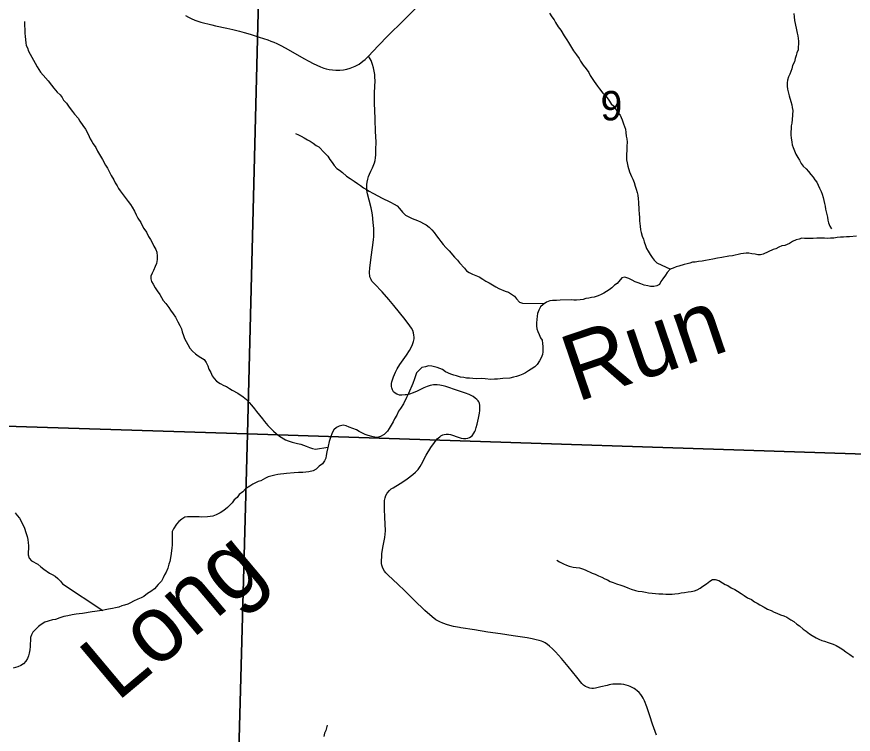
# Model space of a CAD drawing. Extents: x -3.3 to 34, y 0 to 56.8.
# Drawn here: x -0.715 to 0.477, y 29.247 to 30.269 of the extents above; entities that cross this region are included whole.
import ezdxf

# ---------------------------------------------------------------- set-up
doc = ezdxf.new("R2010")
doc.units = 0
for name, color, linetype in [('GM_X_Corporation', 7, 'Continuous'), ('GM_X_County_Road', 7, 'Continuous'), ('GM_X_Section_Text', 7, 'Continuous'), ('GM_X_Township_Road', 7, 'Continuous'), ('GT_Project_Cells', 7, 'Continuous'), ('GT_Project_Soil_Layers', 7, 'Continuous')]:
    doc.layers.add(name, color=color, linetype=linetype)

msp = doc.modelspace()

# ---------------------------------------------------------------- linework, layer by layer
at = {"layer": 'GM_X_Corporation'}
for points in [[(-0.3611, 30.6698), (-0.3862, 29.675), (-1.3918, 29.7067), (-1.3637, 30.7035)], [(-0.3611, 30.6698), (0.6593, 30.6334), (0.6247, 29.6418), (-0.3862, 29.675)], [(-1.3918, 29.7067), (-0.3862, 29.675), (-0.4137, 28.6668), (-1.4193, 28.6974)], [(0.6247, 29.6418), (0.5878, 28.6278), (-0.4137, 28.6668), (-0.3862, 29.675)]]:
    msp.add_lwpolyline(points, close=True, dxfattribs=at)
at = {"layer": 'GM_X_County_Road'}
msp.add_lwpolyline([(-0.4744, 30.271), (-0.4705, 30.2687), (-0.4665, 30.2666), (-0.4613, 30.2645), (-0.4571, 30.263), (-0.4528, 30.2617), (-0.4372, 30.2576), (-0.4317, 30.2564), (-0.4156, 30.253), (-0.4073, 30.2512), (-0.3978, 30.2488), (-0.391, 30.247), (-0.3822, 30.2444), (-0.3695, 30.2403), (-0.3573, 30.2363), (-0.353, 30.2347), (-0.3487, 30.2331), (-0.3446, 30.2312), (-0.3379, 30.2278), (-0.3284, 30.2227), (-0.3059, 30.2098), (-0.2987, 30.2059), (-0.2926, 30.2026), (-0.2873, 30.2003), (-0.2821, 30.198), (-0.2774, 30.1961), (-0.2739, 30.195), (-0.2699, 30.1941), (-0.265, 30.1934), (-0.2603, 30.193), (-0.2548, 30.1932), (-0.2495, 30.1936), (-0.2445, 30.1946), (-0.24, 30.1958), (-0.2329, 30.1989), (-0.2271, 30.2019), (-0.2216, 30.2058), (-0.2183, 30.2084), (-0.2136, 30.2133), (-0.2071, 30.22), (-0.1994, 30.2284), (-0.1861, 30.2423), (-0.1639, 30.264), (-0.1389, 30.2885)], dxfattribs=at)
at = {"layer": 'GM_X_Township_Road'}
for points in [[(-0.0822, 29.3984), (-0.0842, 29.3987), (-0.0927, 29.4004), (-0.101, 29.4026), (-0.1075, 29.4049), (-0.1121, 29.4069), (-0.1175, 29.4099), (-0.1231, 29.4141), (-0.1335, 29.4233), (-0.1488, 29.4379), (-0.1621, 29.451), (-0.1721, 29.4608), (-0.1857, 29.4734), (-0.189, 29.4769), (-0.1907, 29.4791), (-0.1927, 29.4823), (-0.1938, 29.4849), (-0.1946, 29.4876), (-0.195, 29.4899), (-0.1952, 29.4928), (-0.1949, 29.5008), (-0.1945, 29.5042), (-0.1927, 29.5153), (-0.1905, 29.5273), (-0.19, 29.5319), (-0.1897, 29.5365), (-0.1904, 29.5561), (-0.191, 29.5673), (-0.1907, 29.5799), (-0.1899, 29.5836), (-0.1888, 29.5868), (-0.1871, 29.5901), (-0.184, 29.5943), (-0.1813, 29.5964), (-0.1786, 29.5981), (-0.1686, 29.6039), (-0.1633, 29.6072), (-0.1585, 29.6106), (-0.1505, 29.6168), (-0.1465, 29.6203), (-0.1445, 29.6225), (-0.143, 29.6242), (-0.14, 29.6284), (-0.138, 29.6317), (-0.1313, 29.6444), (-0.1247, 29.6555), (-0.1197, 29.6627), (-0.1158, 29.6679), (-0.1122, 29.6708), (-0.1107, 29.6718), (-0.1078, 29.6734), (-0.1059, 29.674), (-0.1031, 29.6743), (-0.0995, 29.6743), (-0.0968, 29.6738), (-0.0845, 29.6698), (-0.0817, 29.6688), (-0.0781, 29.6682), (-0.0749, 29.6681), (-0.0722, 29.6687), (-0.0695, 29.6698), (-0.066, 29.6722), (-0.0634, 29.6759), (-0.0621, 29.6782), (-0.0613, 29.6801), (-0.0601, 29.6839), (-0.0589, 29.6886), (-0.0569, 29.6973), (-0.0554, 29.7042), (-0.055, 29.7079), (-0.0551, 29.7152), (-0.0556, 29.7185), (-0.0564, 29.7205), (-0.0574, 29.7221), (-0.0591, 29.7239), (-0.0615, 29.7259), (-0.0643, 29.7279), (-0.0675, 29.7297), (-0.07, 29.7308), (-0.0753, 29.7328), (-0.0869, 29.7366), (-0.1034, 29.7421), (-0.1074, 29.7433), (-0.1121, 29.7444), (-0.1156, 29.7448), (-0.121, 29.7447), (-0.1234, 29.7443), (-0.1259, 29.7437), (-0.1301, 29.7424), (-0.1347, 29.7405), (-0.1443, 29.7358), (-0.1502, 29.7333), (-0.1551, 29.7316), (-0.1594, 29.7306), (-0.1615, 29.7303), (-0.166, 29.73), (-0.1697, 29.7302), (-0.1718, 29.7308), (-0.1735, 29.7315), (-0.1759, 29.7329), (-0.1781, 29.7346), (-0.1797, 29.7375), (-0.1806, 29.7402), (-0.181, 29.7425), (-0.1811, 29.7449), (-0.1808, 29.7468), (-0.1803, 29.7492), (-0.1779, 29.7562), (-0.175, 29.7629), (-0.1726, 29.7673), (-0.1689, 29.7735), (-0.1596, 29.7868), (-0.1553, 29.7934), (-0.1524, 29.7989), (-0.1508, 29.8024), (-0.1495, 29.8064), (-0.1488, 29.8104), (-0.1486, 29.8128), (-0.1489, 29.8156), (-0.1496, 29.8187), (-0.1507, 29.8222), (-0.1525, 29.8255), (-0.1548, 29.8288), (-0.1614, 29.8377), (-0.1693, 29.8478), (-0.1774, 29.8579), (-0.1845, 29.8662), (-0.1944, 29.8773), (-0.2051, 29.8884), (-0.2075, 29.8909), (-0.2088, 29.8926), (-0.2101, 29.8948), (-0.2108, 29.8965), (-0.2116, 29.8988), (-0.212, 29.9011), (-0.2122, 29.9028), (-0.2121, 29.9051), (-0.2116, 29.9111), (-0.2097, 29.9264), (-0.208, 29.9404), (-0.2066, 29.9513), (-0.2062, 29.956), (-0.2061, 29.9623), (-0.2063, 29.9673), (-0.2069, 29.9759), (-0.2081, 29.9871), (-0.2089, 29.9924), (-0.21, 29.9971), (-0.2128, 30.0077), (-0.2152, 30.017), (-0.2157, 30.0192), (-0.2161, 30.0225), (-0.2162, 30.0259), (-0.2161, 30.03), (-0.2156, 30.0337), (-0.2148, 30.038), (-0.2139, 30.0414), (-0.2125, 30.0451), (-0.2105, 30.0492), (-0.2079, 30.0541), (-0.2059, 30.0586), (-0.205, 30.0612), (-0.2044, 30.0643), (-0.2038, 30.0681), (-0.2034, 30.0723), (-0.2031, 30.0799), (-0.2029, 30.0904), (-0.2036, 30.1061), (-0.2042, 30.1222), (-0.2048, 30.1371), (-0.205, 30.1444), (-0.2051, 30.1518), (-0.205, 30.1615), (-0.2046, 30.1694), (-0.2043, 30.1785), (-0.2045, 30.1828), (-0.2049, 30.1872), (-0.2055, 30.1915), (-0.2065, 30.1963), (-0.2079, 30.2012), (-0.21, 30.2067), (-0.2114, 30.2095), (-0.2136, 30.2133)], [(0.1967, 29.2453), (0.1914, 29.261), (0.1873, 29.2729), (0.1829, 29.286), (0.1797, 29.2942), (0.1778, 29.2982), (0.1764, 29.3007), (0.1745, 29.3033), (0.172, 29.3064), (0.1694, 29.3088), (0.1671, 29.3104), (0.165, 29.3119), (0.1629, 29.3129), (0.1595, 29.3146), (0.157, 29.3156), (0.1537, 29.3167), (0.1501, 29.3175), (0.1465, 29.318), (0.1428, 29.3183), (0.1347, 29.3179), (0.132, 29.3175), (0.1296, 29.317), (0.1267, 29.3164), (0.1174, 29.3142), (0.1098, 29.3124), (0.1071, 29.312), (0.1048, 29.3119), (0.1017, 29.3124), (0.0982, 29.3136), (0.0955, 29.315), (0.0929, 29.3169), (0.0906, 29.3191), (0.0833, 29.328), (0.0709, 29.3432), (0.0613, 29.3549), (0.0529, 29.3642), (0.0484, 29.3686), (0.0441, 29.3723), (0.0413, 29.3744), (0.038, 29.3768), (0.0355, 29.3783), (0.0327, 29.3795), (0.0298, 29.3804), (0.0254, 29.3815), (0.0194, 29.3827), (0.0123, 29.3839), (-0.0077, 29.3869), (-0.0253, 29.3896), (-0.0434, 29.3923), (-0.0627, 29.3954), (-0.0822, 29.3984)]]:
    msp.add_lwpolyline(points, dxfattribs=at)
at = {"layer": 'GT_Project_Soil_Layers'}
for points in [[(0.0445, 30.2746), (0.0476, 30.269), (0.051, 30.2649), (0.053, 30.2611), (0.0569, 30.2551), (0.0607, 30.2502), (0.065, 30.2419), (0.0689, 30.2366), (0.0712, 30.2325), (0.0743, 30.228), (0.0786, 30.2208), (0.0828, 30.2148), (0.0867, 30.21), (0.0886, 30.2058), (0.0925, 30.2002), (0.0967, 30.1949), (0.1002, 30.19), (0.1025, 30.1855), (0.108, 30.1772), (0.1126, 30.1705), (0.1157, 30.1667), (0.1203, 30.1603), (0.1249, 30.1558), (0.1288, 30.1502), (0.1323, 30.1453), (0.1361, 30.142), (0.1384, 30.1382), (0.1419, 30.1329), (0.145, 30.1288), (0.1478, 30.1224), (0.1497, 30.1167), (0.1513, 30.113), (0.1525, 30.1092), (0.1533, 30.1043), (0.1538, 30.0993), (0.1546, 30.0952), (0.155, 30.0906), (0.1547, 30.0849), (0.1548, 30.0808), (0.1541, 30.0709), (0.1542, 30.0652), (0.155, 30.061), (0.1562, 30.0565), (0.1586, 30.0482), (0.161, 30.0414), (0.1633, 30.0376), (0.1649, 30.0331), (0.1665, 30.0278), (0.1681, 30.0236), (0.1693, 30.0187), (0.1701, 30.0149), (0.1705, 30.0096), (0.1713, 30.0051), (0.1715, 29.9941), (0.1723, 29.9884), (0.1728, 29.9831), (0.1728, 29.9782), (0.1737, 29.9706), (0.1741, 29.9657), (0.175, 29.9619), (0.1762, 29.9566), (0.1781, 29.9525), (0.1793, 29.9483), (0.1813, 29.9434), (0.1828, 29.9389), (0.1852, 29.9351), (0.1879, 29.9302), (0.1906, 29.9261), (0.1937, 29.9223), (0.1972, 29.9186), (0.2168, 29.9095)], [(0.3926, 30.2741), (0.393, 30.2692), (0.3938, 30.2639), (0.3947, 30.2597), (0.3963, 30.2506), (0.3975, 30.2461), (0.3983, 30.2423), (0.3992, 30.2347), (0.3992, 30.2306), (0.3989, 30.226), (0.3986, 30.2222), (0.3971, 30.218), (0.396, 30.2142), (0.3946, 30.2096), (0.3935, 30.2051), (0.3909, 30.1997), (0.3898, 30.1952), (0.3869, 30.1875), (0.3851, 30.1837), (0.3836, 30.1791), (0.3833, 30.1753), (0.383, 30.1704), (0.3834, 30.1662), (0.3846, 30.1621), (0.3858, 30.1568), (0.3882, 30.1485), (0.3898, 30.1439), (0.3902, 30.1401), (0.391, 30.1356), (0.3901, 30.1227), (0.3897, 30.1178), (0.389, 30.1136), (0.3887, 30.1098), (0.3884, 30.1048), (0.3885, 30.1007), (0.3889, 30.0969), (0.3897, 30.0904), (0.3905, 30.0867), (0.3917, 30.0829), (0.3937, 30.0783), (0.3957, 30.0734), (0.3984, 30.0685), (0.4007, 30.0648), (0.403, 30.0603), (0.4061, 30.0561), (0.41, 30.0524), (0.4134, 30.0486), (0.4169, 30.0445), (0.4204, 30.0408), (0.4227, 30.037), (0.4254, 30.0333), (0.4293, 30.025), (0.4316, 30.0201), (0.4332, 30.0163), (0.4344, 30.0118), (0.4356, 30.0076), (0.4364, 30.0031), (0.4372, 29.9993), (0.438, 29.9951), (0.4405, 29.9838), (0.4413, 29.9792), (0.4421, 29.9754), (0.4441, 29.9709), (0.4464, 29.9671)], [(-0.7039, 30.2627), (-0.7037, 30.2452), (-0.7033, 30.2414), (-0.7028, 30.2365), (-0.702, 30.2323), (-0.7016, 30.2285), (-0.7, 30.2248), (-0.6984, 30.2202), (-0.6938, 30.2119), (-0.6891, 30.2029), (-0.686, 30.198), (-0.6814, 30.1905), (-0.6775, 30.186), (-0.6702, 30.1781), (-0.6656, 30.1717), (-0.6621, 30.1676), (-0.6575, 30.162), (-0.6532, 30.1579), (-0.6505, 30.1541), (-0.6486, 30.1504), (-0.6444, 30.1459), (-0.6405, 30.1406), (-0.6359, 30.1342), (-0.6328, 30.1305), (-0.6278, 30.1245), (-0.6254, 30.1203), (-0.6208, 30.1143), (-0.6173, 30.1091), (-0.6134, 30.1019), (-0.6103, 30.0955), (-0.608, 30.0917), (-0.606, 30.088), (-0.6025, 30.0827), (-0.6002, 30.0778), (-0.5971, 30.0729), (-0.5928, 30.0658), (-0.5886, 30.0579), (-0.5858, 30.0534), (-0.5831, 30.0477), (-0.5804, 30.0428), (-0.5769, 30.0368), (-0.5749, 30.0326), (-0.5719, 30.0285), (-0.5699, 30.0247), (-0.5676, 30.021), (-0.5649, 30.0172), (-0.5564, 30.006), (-0.5529, 30.0018), (-0.5506, 29.9977), (-0.5471, 29.9924), (-0.5447, 29.9868), (-0.5424, 29.9823), (-0.5381, 29.9759), (-0.5362, 29.9717), (-0.5339, 29.9676), (-0.53, 29.9623), (-0.5273, 29.9563), (-0.5246, 29.9518), (-0.5214, 29.9465), (-0.5195, 29.9424), (-0.5168, 29.9375), (-0.5156, 29.9337), (-0.5148, 29.928), (-0.5151, 29.9234), (-0.5161, 29.9174), (-0.518, 29.9135), (-0.5202, 29.9078), (-0.522, 29.904), (-0.5242, 29.8994), (-0.5242, 29.8956), (-0.523, 29.8918), (-0.5207, 29.8881), (-0.5179, 29.8828), (-0.5152, 29.8787), (-0.5114, 29.8734), (-0.5087, 29.8693), (-0.5063, 29.8651), (-0.5028, 29.8606), (-0.4982, 29.855), (-0.4959, 29.8512), (-0.4924, 29.846), (-0.4889, 29.8411), (-0.4854, 29.8347), (-0.4827, 29.8294), (-0.4804, 29.8245), (-0.4792, 29.82), (-0.4772, 29.8151), (-0.476, 29.8105), (-0.4713, 29.8023), (-0.4682, 29.797), (-0.4648, 29.7929), (-0.4605, 29.7891), (-0.4563, 29.7862), (-0.4525, 29.7836), (-0.4479, 29.7806), (-0.4452, 29.7765), (-0.4429, 29.7716), (-0.4413, 29.767), (-0.4386, 29.7621), (-0.4366, 29.7576), (-0.4335, 29.7535)], [(-0.3176, 30.103), (-0.3134, 30.1008), (-0.3096, 30.099), (-0.3054, 30.0968), (-0.3008, 30.0938), (-0.297, 30.0919), (-0.2924, 30.0893), (-0.2882, 30.086), (-0.2844, 30.0838), (-0.2763, 30.0752), (-0.2717, 30.0707), (-0.2686, 30.0658), (-0.2655, 30.0616), (-0.2628, 30.0575), (-0.2589, 30.053), (-0.2551, 30.0504), (-0.2509, 30.0474), (-0.2452, 30.0422), (-0.2398, 30.0389), (-0.2341, 30.0351), (-0.2295, 30.0314), (-0.2253, 30.0288), (-0.2207, 30.0255), (-0.2164, 30.0229), (-0.2126, 30.0206), (-0.2077, 30.0177), (-0.1993, 30.0136), (-0.1951, 30.0114), (-0.1912, 30.0092), (-0.1863, 30.007), (-0.1825, 30.0051), (-0.1771, 30.0022), (-0.1729, 29.9996), (-0.1694, 29.9958), (-0.1652, 29.991), (-0.161, 29.9865), (-0.1552, 29.9835), (-0.1514, 29.9817), (-0.1438, 29.9787), (-0.1396, 29.9769), (-0.1354, 29.9747), (-0.1316, 29.9728), (-0.127, 29.9695), (-0.1232, 29.9657), (-0.1201, 29.962), (-0.1166, 29.9571), (-0.1135, 29.953), (-0.1108, 29.9492), (-0.1073, 29.9447), (-0.1035, 29.9402), (-0.0989, 29.9357), (-0.0912, 29.9267), (-0.0869, 29.9222), (-0.0838, 29.9185), (-0.0769, 29.911), (-0.0738, 29.9072), (-0.07, 29.9046), (-0.0654, 29.9024), (-0.0608, 29.9006), (-0.0559, 29.8984), (-0.0509, 29.8954), (-0.0463, 29.8924), (-0.0417, 29.8902), (-0.0322, 29.8843), (-0.028, 29.8821), (-0.0188, 29.8784), (-0.0143, 29.8769), (-0.0097, 29.874), (-0.0058, 29.871), (-0.0028, 29.8672), (0.0015, 29.8627), (0.006, 29.8613), (0.0373, 29.8607)], [(0.4822, 29.9566), (0.4719, 29.9557), (0.4678, 29.9557), (0.4636, 29.9552), (0.4594, 29.9552), (0.4545, 29.9547), (0.4496, 29.9539), (0.4447, 29.9535), (0.4405, 29.9534), (0.4363, 29.9537), (0.4253, 29.9536), (0.42, 29.9531), (0.4159, 29.9531), (0.4117, 29.9534), (0.4079, 29.9533), (0.4041, 29.9537), (0.4003, 29.9525), (0.3962, 29.9513), (0.3909, 29.9489), (0.3864, 29.9462), (0.3796, 29.9435), (0.3754, 29.9426), (0.3713, 29.9411), (0.3668, 29.9387), (0.363, 29.9375), (0.349, 29.9309), (0.3449, 29.9301), (0.3411, 29.93), (0.3373, 29.9307), (0.3327, 29.9314), (0.3285, 29.9321), (0.3248, 29.9325), (0.3172, 29.9316), (0.3134, 29.9304), (0.3092, 29.9296), (0.3051, 29.9284), (0.2998, 29.9279), (0.2899, 29.9263), (0.2839, 29.9251), (0.2771, 29.9238), (0.2718, 29.923), (0.2665, 29.9218), (0.262, 29.921), (0.2567, 29.9205), (0.2521, 29.9197), (0.2483, 29.9193), (0.2446, 29.9181), (0.2404, 29.9173), (0.2362, 29.9161), (0.2287, 29.9137), (0.2249, 29.9129), (0.2208, 29.9109), (0.2162, 29.9093), (0.2121, 29.9047), (0.2099, 29.9009)], [(0.2099, 29.9009), (0.2058, 29.8959), (0.2032, 29.8921), (0.201, 29.8879), (0.1972, 29.8856), (0.1931, 29.8847), (0.1885, 29.8847), (0.1847, 29.8858), (0.1794, 29.8868), (0.1744, 29.8887), (0.1706, 29.8901), (0.1664, 29.8916), (0.1622, 29.8938), (0.1573, 29.896), (0.1519, 29.8982), (0.1474, 29.8974), (0.1407, 29.889), (0.1369, 29.8866), (0.1332, 29.8828), (0.1294, 29.8801), (0.1219, 29.8754), (0.1181, 29.8735), (0.1136, 29.8715), (0.1079, 29.8695), (0.1042, 29.8691), (0.1004, 29.8683), (0.0962, 29.8675), (0.0921, 29.8663), (0.0879, 29.8658), (0.083, 29.8654), (0.0792, 29.8653), (0.075, 29.8657), (0.0595, 29.8654), (0.0542, 29.865), (0.0485, 29.8649), (0.0447, 29.8645), (0.0402, 29.8625), (0.0353, 29.8594), (0.0315, 29.856), (0.0289, 29.851), (0.0271, 29.8464), (0.0268, 29.8426), (0.0261, 29.838), (0.0258, 29.8331), (0.0258, 29.8289), (0.0263, 29.8244), (0.0275, 29.8206), (0.0294, 29.8165), (0.0314, 29.8119), (0.0337, 29.8082), (0.0345, 29.8036), (0.0349, 29.7991), (0.035, 29.7915), (0.0343, 29.7877), (0.0325, 29.7831), (0.0299, 29.7789), (0.0269, 29.7739), (0.0232, 29.7705), (0.0183, 29.767), (0.0142, 29.7647), (0.01, 29.7616), (0.0063, 29.76), (0.0014, 29.758), (-0.0028, 29.7568), (-0.0069, 29.7556), (-0.0122, 29.7544), (-0.0221, 29.7535), (-0.0259, 29.7531), (-0.0297, 29.753), (-0.0342, 29.7526), (-0.0395, 29.7525), (-0.0475, 29.7532), (-0.052, 29.7535), (-0.06, 29.7534), (-0.0649, 29.7537), (-0.0695, 29.754), (-0.074, 29.7543), (-0.0778, 29.755), (-0.0824, 29.7557), (-0.0881, 29.7575), (-0.0919, 29.7586), (-0.0961, 29.7597), (-0.1037, 29.7634), (-0.108, 29.7664), (-0.1156, 29.7693), (-0.1198, 29.7704), (-0.1236, 29.7715), (-0.1281, 29.7718), (-0.1326, 29.7702), (-0.1376, 29.7694), (-0.1417, 29.7655), (-0.1454, 29.7617), (-0.1465, 29.7575), (-0.1483, 29.7533), (-0.1505, 29.7468), (-0.1568, 29.7323), (-0.1597, 29.7266), (-0.1638, 29.7178), (-0.1683, 29.7109), (-0.1709, 29.7071), (-0.1734, 29.7013)], [(-0.4335, 29.7535), (-0.4304, 29.7497), (-0.4251, 29.7464), (-0.4201, 29.7438), (-0.4163, 29.7423), (-0.4117, 29.7397), (-0.4079, 29.7371), (-0.4002, 29.7327), (-0.3926, 29.7275), (-0.3876, 29.7238), (-0.3838, 29.7196), (-0.3803, 29.7155), (-0.3761, 29.7106), (-0.3734, 29.7069), (-0.3691, 29.7013), (-0.3649, 29.6964), (-0.3618, 29.6926), (-0.3572, 29.6866), (-0.3491, 29.6788), (-0.3452, 29.6754), (-0.3406, 29.6717), (-0.3322, 29.6665), (-0.3284, 29.665), (-0.3227, 29.6628), (-0.3189, 29.6621), (-0.3151, 29.661), (-0.3102, 29.66), (-0.3063, 29.6585), (-0.3025, 29.6574), (-0.298, 29.6556), (-0.2934, 29.6541), (-0.2892, 29.6531), (-0.2715, 29.6557)], [(-0.1734, 29.7013), (-0.1764, 29.6964), (-0.1786, 29.6918), (-0.1816, 29.6872), (-0.1842, 29.6826), (-0.1868, 29.6788), (-0.1916, 29.6741), (-0.1965, 29.671), (-0.2007, 29.6698), (-0.2045, 29.6702), (-0.209, 29.6709), (-0.214, 29.6723), (-0.2186, 29.6738), (-0.227, 29.6782), (-0.2308, 29.6804), (-0.2361, 29.6826), (-0.2411, 29.6845), (-0.2457, 29.6863), (-0.2498, 29.6874), (-0.2555, 29.6858), (-0.2593, 29.6838), (-0.263, 29.6804), (-0.2656, 29.6761), (-0.2678, 29.6697), (-0.2696, 29.664), (-0.2711, 29.6575), (-0.2732, 29.6491), (-0.2739, 29.6442), (-0.2746, 29.6404), (-0.2765, 29.6365), (-0.2794, 29.6323), (-0.2839, 29.6288), (-0.2881, 29.6246), (-0.2926, 29.6223), (-0.2986, 29.6207), (-0.3073, 29.6198), (-0.3134, 29.6197), (-0.3195, 29.6192), (-0.3304, 29.6183), (-0.3342, 29.6179), (-0.3392, 29.6174), (-0.3429, 29.617), (-0.3471, 29.6158), (-0.3528, 29.6146), (-0.3565, 29.6134), (-0.3607, 29.6115), (-0.3671, 29.6079), (-0.3709, 29.6068), (-0.3784, 29.6029), (-0.3829, 29.6001), (-0.3889, 29.5966), (-0.393, 29.5924), (-0.3979, 29.5885), (-0.4009, 29.5839), (-0.405, 29.5809), (-0.408, 29.5766), (-0.4147, 29.5701), (-0.42, 29.5658), (-0.4253, 29.5624), (-0.4309, 29.5596), (-0.4354, 29.5577), (-0.4392, 29.5572), (-0.4434, 29.5564), (-0.4513, 29.5563), (-0.4551, 29.5566), (-0.4718, 29.5564), (-0.4756, 29.556), (-0.4797, 29.5532), (-0.4839, 29.5498), (-0.4876, 29.5459), (-0.4917, 29.5394), (-0.4935, 29.5356), (-0.4935, 29.5307), (-0.4938, 29.5269), (-0.4934, 29.5227), (-0.4937, 29.5162), (-0.494, 29.5124), (-0.4947, 29.5083), (-0.4957, 29.501), (-0.4971, 29.493), (-0.4982, 29.4889), (-0.4997, 29.4835), (-0.5022, 29.4778), (-0.5045, 29.474), (-0.5063, 29.4698), (-0.5089, 29.4648), (-0.5134, 29.4602), (-0.519, 29.454), (-0.5242, 29.4502), (-0.5288, 29.4474), (-0.534, 29.4428), (-0.5378, 29.4409), (-0.5423, 29.4393), (-0.5487, 29.4362), (-0.5528, 29.4338), (-0.557, 29.4322), (-0.5615, 29.4307), (-0.5653, 29.4295), (-0.5694, 29.4279), (-0.5744, 29.4267), (-0.5785, 29.4259)], [(-0.7176, 29.5624), (-0.7146, 29.5586), (-0.7111, 29.5545), (-0.7045, 29.5417), (-0.7017, 29.533), (-0.7001, 29.5285), (-0.6993, 29.5243), (-0.6989, 29.5194), (-0.6984, 29.5156), (-0.6984, 29.5111), (-0.6991, 29.5069), (-0.699, 29.5023), (-0.6974, 29.4978), (-0.6943, 29.494), (-0.6852, 29.4889), (-0.6806, 29.4855), (-0.6767, 29.4822), (-0.6683, 29.4762), (-0.6645, 29.4744), (-0.6603, 29.4718), (-0.6565, 29.4688)], [(0.055, 29.4947), (0.0588, 29.4925), (0.0645, 29.4895), (0.0687, 29.4877), (0.0725, 29.4862), (0.0779, 29.4848), (0.0824, 29.4844), (0.087, 29.4837), (0.0915, 29.4823), (0.0954, 29.4808), (0.1053, 29.4764), (0.1095, 29.475), (0.1144, 29.4727), (0.119, 29.4705), (0.1232, 29.4683), (0.127, 29.4668), (0.1308, 29.4646), (0.135, 29.4632), (0.14, 29.4613), (0.1461, 29.4591), (0.1503, 29.4577), (0.156, 29.4555), (0.1609, 29.4537), (0.167, 29.4518), (0.1708, 29.4508), (0.1762, 29.4501), (0.1811, 29.449), (0.1853, 29.4483), (0.1906, 29.4476), (0.1955, 29.4473), (0.2001, 29.447), (0.2058, 29.4467), (0.2103, 29.4464), (0.2194, 29.4465), (0.2232, 29.4469), (0.2281, 29.4474), (0.2319, 29.4482), (0.2369, 29.4486), (0.2418, 29.4498), (0.2463, 29.4503), (0.2512, 29.4511), (0.255, 29.4527), (0.2591, 29.455), (0.2629, 29.4577), (0.2682, 29.4612), (0.2727, 29.4651), (0.2768, 29.4674), (0.2806, 29.4674), (0.2855, 29.4656), (0.2909, 29.4627), (0.2947, 29.4601), (0.2985, 29.4586), (0.3035, 29.4552), (0.3085, 29.453), (0.3123, 29.4508), (0.3176, 29.4475), (0.3218, 29.4445), (0.3264, 29.4411), (0.3322, 29.4386), (0.3368, 29.4352), (0.3406, 29.4334), (0.3444, 29.4311), (0.3505, 29.4278), (0.3551, 29.4252), (0.3604, 29.423), (0.3646, 29.4208), (0.3684, 29.4193), (0.3738, 29.4167), (0.3784, 29.4153), (0.3829, 29.4135), (0.3883, 29.4097), (0.3925, 29.4075), (0.3967, 29.4038), (0.4005, 29.4012), (0.4059, 29.3963), (0.4101, 29.3937), (0.4151, 29.39), (0.4189, 29.3874), (0.4247, 29.3841), (0.4285, 29.3822), (0.4327, 29.3804), (0.4365, 29.3793), (0.4414, 29.3775), (0.4487, 29.3753), (0.4529, 29.3734), (0.4586, 29.3697), (0.4624, 29.3675), (0.467, 29.3642), (0.4724, 29.3604), (0.4777, 29.3567)], [(-0.6565, 29.4688), (-0.6526, 29.4647), (-0.6499, 29.4609), (-0.5925, 29.4233)], [(-0.5785, 29.4259), (-0.5842, 29.425), (-0.5891, 29.4242), (-0.5936, 29.423), (-0.5974, 29.4226), (-0.6039, 29.4217), (-0.6077, 29.4213), (-0.6213, 29.4188), (-0.6262, 29.4184), (-0.6304, 29.4179), (-0.636, 29.4167), (-0.6421, 29.4155), (-0.6481, 29.4146), (-0.6538, 29.4127), (-0.6598, 29.4103), (-0.664, 29.4099), (-0.6704, 29.4079), (-0.6753, 29.4063), (-0.6802, 29.4032), (-0.684, 29.4005), (-0.6885, 29.3959), (-0.6922, 29.3924), (-0.6941, 29.3886), (-0.6955, 29.3847), (-0.6955, 29.3802), (-0.6958, 29.3756), (-0.6961, 29.3718), (-0.6964, 29.3669), (-0.6975, 29.3623), (-0.6982, 29.3585), (-0.7, 29.3547), (-0.7023, 29.3509), (-0.7056, 29.347), (-0.7094, 29.3447), (-0.7135, 29.3428), (-0.7203, 29.3411)], [(-0.2725, 29.2598), (-0.2747, 29.2522), (-0.2765, 29.2484), (-0.2776, 29.2434)]]:
    msp.add_lwpolyline(points, dxfattribs=at)

# ---------------------------------------------------------------- texts
at = {"layer": 'GM_X_Section_Text'}
msp.add_text('9', height=0.0419, rotation=0, dxfattribs=at).set_placement((0.117, 30.1216))
at = {"layer": 'GT_Project_Cells'}
for s, height, rotation, p in [('Run', 0.0947, 18.7958, (0.0832, 29.7198)), ('Long', 0.09471, 40.0287, (-0.5721, 29.2919))]:
    msp.add_text(s, height=height, rotation=rotation, dxfattribs=at).set_placement(p)

doc.saveas('drawing.dxf')
